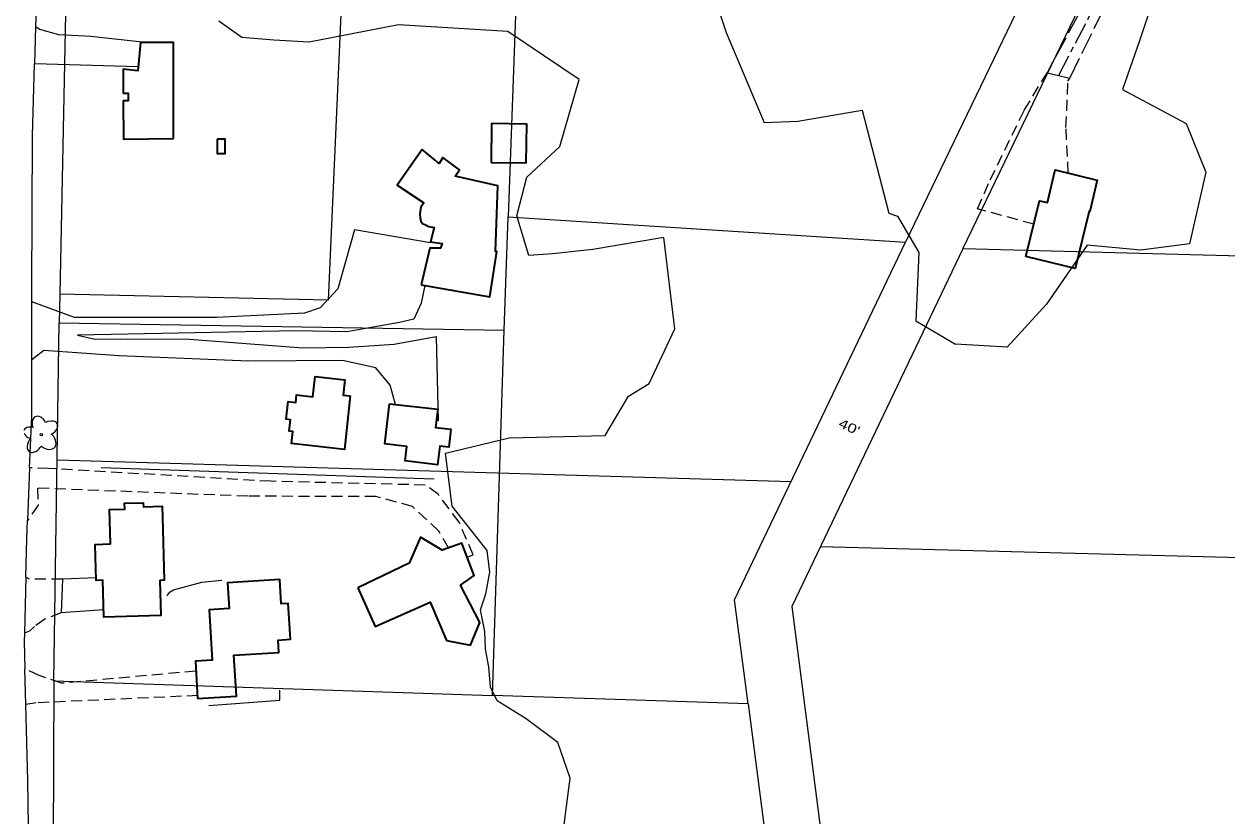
# Model space of a CAD drawing. Extents: x -861682 to -858969, y -1797841 to -1795153.
# Drawn here: x -860350 to -859566, y -1797317 to -1796801 of the extents above; entities that cross this region are included whole.
import ezdxf

# ---------------------------------------------------------------- set-up
doc = ezdxf.new("R2010")
doc.units = 0
doc.header["$LTSCALE"] = 2.4
for name, pattern in [('LONG_DASH_SHORT_DASH', [9.9, 6, -1.2, 1.5, -1.2]), ('LONG_DASHED', [7.5, 6, -1.5]), ('MEDIUM_DASHED', [4.5, 3, -1.5])]:
    doc.linetypes.add(name, pattern=pattern)
for name, color, linetype, lineweight in [('10', 7, 'Continuous', 25), ('11', 7, 'Continuous', 13), ('12', 7, 'Continuous', 35), ('14', 7, 'Continuous', 25), ('17', 7, 'Continuous', 13), ('18', 7, 'Continuous', 13), ('30', 7, 'Continuous', 13), ('32', 7, 'LONG_DASH_SHORT_DASH', 13), ('42', 7, 'Continuous', 25)]:
    doc.layers.add(name, color=color, linetype=linetype, lineweight=lineweight)
doc.layers.add('43', color=7, linetype='Continuous')

msp = doc.modelspace()

# ---------------------------------------------------------------- linework, layer by layer
at = {"layer": '10'}
for p, q in [((-860342.31, -1796802.996), (-860343.031, -1796827.034)), ((-860346.245, -1797090.471), (-860347.639, -1797124.877)), ((-860348.726, -1797161.801), (-860349.612, -1797198.32)), ((-860348.717, -1797244.699), (-860349.292, -1797221.563))]:
    msp.add_line(p, q, dxfattribs=at)
at = {"layer": '10', "linetype": 'LONG_DASHED'}
msp.add_line((-859682.764, -1796832.89), (-859668.064, -1796836.421), dxfattribs=at)
for points in [[(-859668.064, -1796836.421), (-859618.333, -1796735.875), (-859614.251, -1796693.585), (-859611.278, -1796669.249), (-859613.515, -1796641.39), (-859636.367, -1796537.57), (-859639.052, -1796515.854), (-859640.064, -1796499.091), (-859638.504, -1796475.704), (-859634.279, -1796469.311), (-859628.446, -1796464.842)], [(-859628.935, -1796662.366), (-859629.064, -1796675.624), (-859629.786, -1796689.577), (-859631.349, -1796697.997), (-859630.873, -1796709.492), (-859631.124, -1796726.244), (-859636.709, -1796746.812), (-859682.764, -1796832.89)]]:
    msp.add_lwpolyline(points, dxfattribs=at)
at = {"layer": '10'}
for points in [[(-860341.964, -1796781.747), (-860341.95, -1796790.964), (-860342.31, -1796802.996)], [(-860344.773, -1796982.253), (-860344.759, -1796973.527), (-860344.449, -1796874.338), (-860343.031, -1796827.034)], [(-860346.245, -1797090.471), (-860344.896, -1797057.128), (-860344.835, -1797020.044), (-860344.773, -1796982.253)], [(-860348.726, -1797161.801), (-860348.119, -1797136.726), (-860347.639, -1797124.877)], [(-860349.612, -1797198.32), (-860349.74, -1797203.566), (-860349.292, -1797221.563)], [(-860346.092, -1797386.021), (-860346.181, -1797383.977), (-860347.486, -1797294.242), (-860348.717, -1797244.699)]]:
    msp.add_lwpolyline(points, dxfattribs=at)
at = {"layer": '11'}
for p, q in [((-860275.382, -1796829.054), (-860343.031, -1796827.034)), ((-860324.869, -1797163.083), (-860325.725, -1797185.049)), ((-860302.946, -1797162.238), (-860324.869, -1797163.083)), ((-860298.008, -1797183), (-860325.725, -1797185.049))]:
    msp.add_line(p, q, dxfattribs=at)
for points in [[(-860270.813, -1796813.231), (-860306.395, -1796809.382), (-860327.239, -1796808.145), (-860339.533, -1796804.652), (-860342.31, -1796802.996)], [(-860084.794, -1796943.821), (-860134.49, -1796935.369), (-860145.2, -1796973.67), (-860156.722, -1796986.233), (-860167.1, -1796989.581), (-860224.476, -1796992.409), (-860317.052, -1796992.545), (-860344.773, -1796982.253)], [(-860088.543, -1796971.501), (-860090.845, -1796983.135), (-860095.762, -1796993.546), (-860104.964, -1796995.708), (-860139.42, -1797001.75), (-860172.957, -1797001.176), (-860315.117, -1797003.873), (-860303.534, -1797006.66), (-860282.281, -1797006.339), (-860241.895, -1797006.649), (-860168.189, -1797012.256), (-860138.198, -1797011.9), (-860108.449, -1797009.892), (-860081.075, -1797004.822), (-860079.91, -1797059.844), (-860081.024, -1797059.59)], [(-860107.698, -1797049.086), (-860111.176, -1797036.589), (-860120.432, -1797025.29), (-860142.179, -1797020.418), (-860203.343, -1797020.899), (-860287.904, -1797017.461), (-860337.04, -1797013.879), (-860344.835, -1797020.044)]]:
    msp.add_lwpolyline(points, dxfattribs=at)
at = {"layer": '11', "linetype": 'MEDIUM_DASHED'}
for points in [[(-859691.464, -1796931.666), (-859728.112, -1796921.702), (-859719.922, -1796902.777), (-859697.669, -1796857.344), (-859682.764, -1796832.89)], [(-859668.964, -1796898.276), (-859670.465, -1796868.571), (-859669.169, -1796838.337), (-859668.064, -1796836.421)], [(-860060.982, -1797148.625), (-860057.123, -1797147.13), (-860066.182, -1797125.912), (-860079.716, -1797107.781), (-860088.242, -1797101.675), (-860188.858, -1797099.246), (-860333.897, -1797090.854), (-860346.245, -1797090.471)], [(-860073.139, -1797142.688), (-860079.384, -1797131.632), (-860096.688, -1797115.643), (-860120.567, -1797109.126), (-860203.934, -1797108.988), (-860341.167, -1797103.636), (-860340.65, -1797114.734), (-860347.639, -1797124.877)], [(-860324.869, -1797163.083), (-860346.36, -1797162.933), (-860348.726, -1797161.801)], [(-860325.725, -1797185.049), (-860336.336, -1797189.106), (-860343.166, -1797193.857), (-860346.224, -1797196.939), (-860349.612, -1797198.32)], [(-860237.781, -1797222.927), (-860325.541, -1797230.864), (-860339.968, -1797225.726), (-860349.292, -1797221.563)], [(-860236.44, -1797238.892), (-860342.022, -1797243.682), (-860348.717, -1797244.699)]]:
    msp.add_lwpolyline(points, dxfattribs=at)
at = {"layer": '12'}
for points in [[(-860252.338, -1796875.856), (-860252.507, -1796813.231), (-860274.038, -1796813.231), (-860275.602, -1796831.635), (-860285.345, -1796830.578), (-860285.201, -1796846.228), (-860281.977, -1796846.198), (-860281.931, -1796851.177), (-860285.263, -1796851.208), (-860285.031, -1796876.16)], [(-860045.396, -1796891.32), (-860022.487, -1796891.701), (-860022.067, -1796866.47), (-860044.976, -1796866.088)], [(-860223.998, -1796876.216), (-860223.96, -1796885.662), (-860218.764, -1796885.641), (-860218.802, -1796876.195)], [(-860090.892, -1796971.089), (-860046.226, -1796978.94), (-860041.621, -1796949.401), (-860042.565, -1796949.405), (-860040.847, -1796906.651), (-860068.739, -1796900.387), (-860065.922, -1796896.125), (-860076.818, -1796888.139), (-860079.163, -1796892.163), (-860090.3, -1796882.997), (-860106.502, -1796906.206), (-860089.217, -1796917.71), (-860091.094, -1796920.551), (-860091.555, -1796923.387), (-860091.786, -1796924.805), (-860091.539, -1796927.402), (-860091.058, -1796929.761), (-860090.107, -1796931.175), (-860088.214, -1796932.112), (-860085.849, -1796933.047), (-860082.54, -1796933.742), (-860084.863, -1796943.198), (-860077.303, -1796944.112), (-860078.235, -1796947.186), (-860085.32, -1796947.214)], [(-859696.576, -1796952.747), (-859687.748, -1796916.342), (-859682.626, -1796917.584), (-859677.446, -1796896.22), (-859650.061, -1796902.86), (-859655.021, -1796923.314), (-859655.46, -1796923.207), (-859664.561, -1796960.55)], [(-860137.125, -1797043.539), (-860141, -1797078.507), (-860175.386, -1797074.696), (-860174.515, -1797066.84), (-860176.967, -1797066.568), (-860176.134, -1797059.062), (-860178.885, -1797058.757), (-860177.604, -1797047.205), (-860172.648, -1797047.755), (-860172.117, -1797042.967), (-860161.559, -1797044.138), (-860160.097, -1797030.959), (-860140.739, -1797033.106), (-860141.838, -1797043.016)], [(-860111.599, -1797048.633), (-860080.175, -1797052.286), (-860081.543, -1797064.052), (-860071.497, -1797065.22), (-860072.861, -1797076.955), (-860078.8, -1797076.265), (-860080.208, -1797088.388), (-860101.308, -1797085.937), (-860100.222, -1797076.588), (-860114.651, -1797074.912)], [(-860259.611, -1797122.908), (-860258.503, -1797163.759), (-860261.341, -1797163.836), (-860260.721, -1797186.685), (-860297.881, -1797187.693), (-860298.532, -1797163.697), (-860302.904, -1797163.816), (-860303.543, -1797140.341), (-860293.506, -1797140.068), (-860294.117, -1797117.615), (-860284.195, -1797117.345), (-860284.298, -1797113.562), (-860272.157, -1797113.231), (-860272.085, -1797115.871), (-860259.812, -1797115.536)], [(-860132.135, -1797168.682), (-860120.934, -1797193.907), (-860085.101, -1797177.94), (-860074.374, -1797202.931), (-860058.775, -1797205.938), (-860052.693, -1797191.272), (-860065.307, -1797166.998), (-860056.359, -1797160.585), (-860064.472, -1797139.599), (-860077.207, -1797144.138), (-860091.411, -1797135.693), (-860098.664, -1797152.489)], [(-860236.703, -1797240.897), (-860211.439, -1797239.378), (-860213.052, -1797212.547), (-860183.774, -1797210.787), (-860184.261, -1797202.681), (-860176.188, -1797202.196), (-860177.592, -1797178.821), (-860182.144, -1797179.094), (-860183.093, -1797163.269), (-860217.242, -1797165.317), (-860216.231, -1797182.172), (-860229.118, -1797182.945), (-860227.151, -1797215.735), (-860238.173, -1797216.396)]]:
    msp.add_lwpolyline(points, close=True, dxfattribs=at)
at = {"layer": '14'}
msp.add_line((-860082.354, -1797097.873), (-860299.655, -1797090.481), dxfattribs=at)
for points in [[(-860256.574, -1797173.908), (-860256.339, -1797173.435), (-860254.695, -1797171.302), (-860252.339, -1797169.876), (-860233.937, -1797165.079), (-860220.954, -1797163.61)], [(-860229.364, -1797245.355), (-860183.09, -1797241.863), (-860183.116, -1797235.312)]]:
    msp.add_lwpolyline(points, dxfattribs=at)
at = {"layer": '17'}
for points in [[(-860338.528, -1797076.323), (-860337.486, -1797077.091), (-860336.08, -1797077.813), (-860334.832, -1797078.219), (-860333.46, -1797078.415), (-860332.442, -1797078.365), (-860331.298, -1797078.075), (-860330.366, -1797077.523), (-860329.626, -1797076.735), (-860329.158, -1797075.777), (-860328.948, -1797074.699), (-860329.052, -1797073.503), (-860329.342, -1797072.331), (-860329.828, -1797071.271), (-860330.55, -1797070.127), (-860331.416, -1797069.207), (-860332.098, -1797068.595), (-860330.916, -1797067.879), (-860329.77, -1797066.931), (-860328.85, -1797065.839), (-860328.328, -1797064.983), (-860327.996, -1797064.169), (-860327.85, -1797063.353), (-860327.89, -1797062.591), (-860328.106, -1797061.911), (-860328.364, -1797061.459), (-860328.784, -1797060.985), (-860329.244, -1797060.631), (-860329.81, -1797060.341), (-860331.046, -1797060.013), (-860332.288, -1797059.979), (-860334.334, -1797060.355), (-860335.994, -1797060.993), (-860336.784, -1797059.415), (-860337.438, -1797058.601), (-860337.85, -1797058.199), (-860338.314, -1797057.799), (-860338.916, -1797057.407), (-860339.92, -1797056.975), (-860340.934, -1797056.805), (-860341.822, -1797056.905), (-860342.622, -1797057.239), (-860343.288, -1797057.725), (-860343.848, -1797058.431), (-860344.198, -1797059.187), (-860344.356, -1797059.625), (-860344.524, -1797060.301), (-860344.576, -1797061.463), (-860344.504, -1797062.361), (-860344.292, -1797063.323), (-860344.008, -1797064.129), (-860345.45, -1797063.897), (-860346.808, -1797063.947), (-860347.966, -1797064.233), (-860348.854, -1797064.731), (-860349.294, -1797065.075), (-860349.728, -1797065.641), (-860349.966, -1797066.175)], [(-860349.888, -1797067.957), (-860349.432, -1797068.769), (-860348.808, -1797069.531), (-860348.03, -1797070.147), (-860347.332, -1797070.571), (-860346.668, -1797070.859), (-860345.94, -1797071.097), (-860346.624, -1797072.309), (-860347.246, -1797073.677), (-860347.642, -1797075.179), (-860347.776, -1797076.513), (-860347.766, -1797077.603), (-860347.432, -1797078.621), (-860346.91, -1797079.467), (-860346.352, -1797079.903), (-860345.966, -1797080.149), (-860345.232, -1797080.373), (-860344.438, -1797080.385), (-860343.668, -1797080.261), (-860343.008, -1797080.049), (-860342.264, -1797079.727), (-860341.188, -1797079.047), (-860340.226, -1797078.261), (-860339.27, -1797077.243), (-860338.524, -1797076.333)]]:
    msp.add_lwpolyline(points, dxfattribs=at)
msp.add_circle((-860338.708, -1797068.911), 0.773, dxfattribs=at)
at = {"layer": '18'}
for points in [[(-859918.287, -1796728.096), (-859891.994, -1796806.633), (-859867.198, -1796865.338), (-859845.238, -1796864.542), (-859803.466, -1796857.29), (-859785.957, -1796924.526), (-859780.284, -1796926.396), (-859766.491, -1796950.193), (-859768.438, -1796994.599), (-859742.62, -1797009.943)], [(-859597.645, -1796737.407), (-859622.316, -1796811.496), (-859633.64, -1796843.735), (-859592.123, -1796865.992), (-859579.268, -1796897.818), (-859589.858, -1796944.544), (-859621.656, -1796948.67), (-859656.557, -1796945.245), (-859683.276, -1796983.809), (-859708.893, -1797011.734), (-859742.62, -1797009.943)], [(-860005.243, -1796950.904), (-860020.825, -1796952.147), (-860028.486, -1796926.2), (-860021.975, -1796900.904), (-860000.564, -1796880.981), (-859987.986, -1796837.24), (-860034.399, -1796806.017), (-860105.738, -1796801.579), (-860164.025, -1796812.913), (-860186.939, -1796811.589), (-860207.965, -1796810.021), (-860222.887, -1796799.219)], [(-860000.133, -1797341.493), (-859993.716, -1797292.818), (-860001.839, -1797269.47), (-860022.447, -1797253.966), (-860041.387, -1797242.234), (-860045.673, -1797233.514), (-860046.908, -1797220.058), (-860049.08, -1797208.732), (-860049.363, -1797197.162), (-860052.254, -1797183.004), (-860048.753, -1797172.599), (-860046.212, -1797158.419), (-860047.922, -1797144.256), (-860070.709, -1797115.536), (-860075.099, -1797080.837), (-860033.574, -1797070.988), (-859970.997, -1797069.321), (-859955.749, -1797043.754), (-859942.321, -1797035.434), (-859925.46, -1796999.942), (-859932.784, -1796940.222), (-859979.04, -1796948.201), (-860005.243, -1796950.904)]]:
    msp.add_lwpolyline(points, dxfattribs=at)
at = {"layer": '30'}
for p, q in [((-859015.656, -1796966.547), (-859737.749, -1796947.769)), ((-860044.409, -1797238.795), (-860036.814, -1797000.716)), ((-859849.752, -1797099.5), (-860328.262, -1797085.395)), ((-859020.232, -1797163.052), (-859830.702, -1797141.975)), ((-860330.383, -1797229.358), (-860044.409, -1797238.795)), ((-859877.808, -1797244.282), (-860044.409, -1797238.795))]:
    msp.add_line(p, q, dxfattribs=at)
for points in [[(-860026.049, -1796707.275), (-860029.004, -1796783.27), (-860034.257, -1796926.914)], [(-860142.618, -1796779.921), (-860151.652, -1796981.121), (-860326.603, -1796977.139)], [(-860326.943, -1796995.888), (-860036.814, -1797000.716), (-860034.257, -1796926.914), (-859775.171, -1796943.35)]]:
    msp.add_lwpolyline(points, dxfattribs=at)
at = {"layer": '32'}
msp.add_lwpolyline([(-859646.986, -1796441.659), (-859648.32, -1796490.003), (-859645.563, -1796523.079), (-859640.663, -1796553.399), (-859625.656, -1796618.021), (-859621.675, -1796639.153), (-859620.144, -1796654.466), (-859619.837, -1796669.473), (-859622.287, -1796700.099), (-859626.531, -1796738.59), (-859635.941, -1796758.82), (-859675.317, -1796834.679)], dxfattribs=at)
at = {"layer": '42'}
for p, q in [((-859737.749, -1796947.769), (-859634.674, -1796733.987)), ((-860322.443, -1796774.784), (-860326.603, -1796977.139)), ((-860326.603, -1796977.139), (-860326.943, -1796995.888)), ((-860330.383, -1797229.358), (-860326.943, -1796995.888)), ((-860330.383, -1797229.358), (-860331.158, -1797380.209)), ((-859877.808, -1797244.282), (-859858.095, -1797395.812))]:
    msp.add_line(p, q, dxfattribs=at)
for points in [[(-859659.085, -1796641.503), (-859646.306, -1796641.548), (-859642.853, -1796668.529), (-859775.171, -1796943.35)], [(-859877.808, -1797244.282), (-859886.549, -1797176.543), (-859775.171, -1796943.35)], [(-859737.749, -1796947.769), (-859849.278, -1797180.786), (-859830.296, -1797327.703)]]:
    msp.add_lwpolyline(points, dxfattribs=at)

# ---------------------------------------------------------------- texts
at = {"layer": '43', "width": 1.35}
msp.add_text("40'", height=6, rotation=334.47, dxfattribs=at).set_placement((-859819.37, -1797063.391))

doc.saveas('drawing.dxf')
